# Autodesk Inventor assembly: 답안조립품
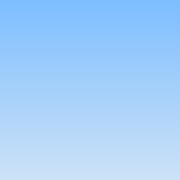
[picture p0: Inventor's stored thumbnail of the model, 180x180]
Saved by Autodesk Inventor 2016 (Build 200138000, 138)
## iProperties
Created: 2018-01
Part Number: 답안조립품
Material: 일반
Document SubType Name: Assembly
Designer: Administrator
Author: Administrator
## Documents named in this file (1)
- C:\Users\Administrator\Desktop\480107V1022\답안조립품.iam
